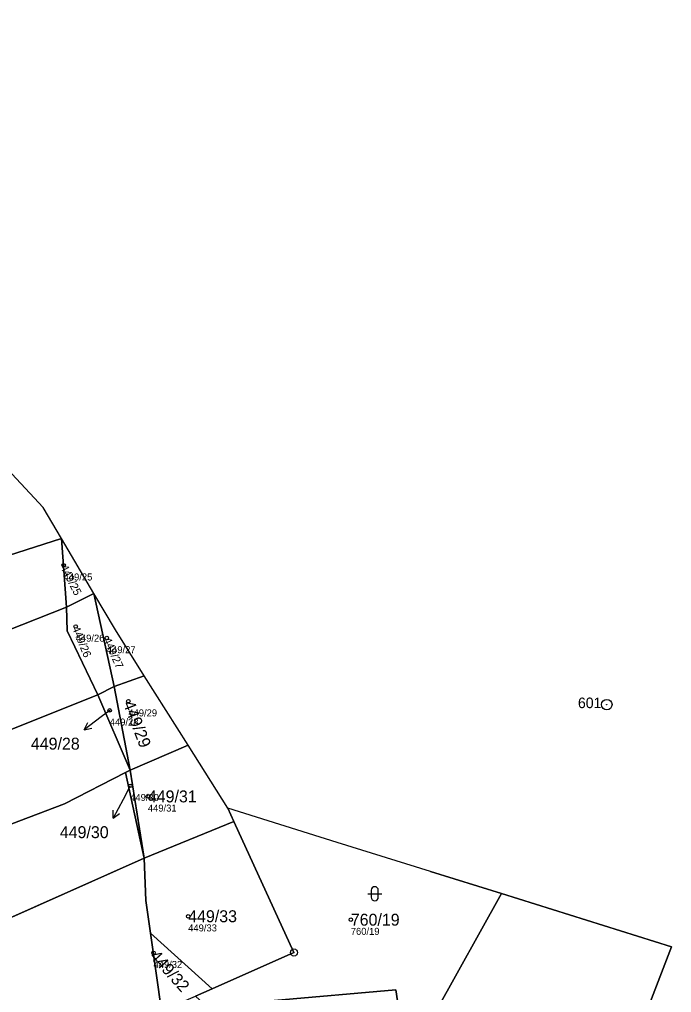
# Model space of a CAD drawing. Extents: x -732749 to -730903, y -1025757 to -1023435.
# Drawn here: x -732119.9 to -732027, y -1025438.1 to -1025299.6 of the extents above; entities that cross this region are included whole.
import ezdxf

# ---------------------------------------------------------------- set-up
doc = ezdxf.new("R2010")
doc.units = 0
for name, color, linetype in [('Definiční body', 7, 'Continuous'), ('Hranice parcel', 7, 'Continuous'), ('Parcelní čísla', 7, 'Continuous'), ('Polygon ku', 7, 'Continuous'), ('Polygon parcely', 7, 'Continuous'), ('Pop  PČ popisy', 7, 'Continuous'), ('Značky bodu BP', 7, 'Continuous'), ('Značky kultur', 7, 'Continuous')]:
    doc.layers.add(name, color=color, linetype=linetype)

msp = doc.modelspace()

# ---------------------------------------------------------------- linework, layer by layer
at = {"layer": 'Definiční body'}
for centre in [(-732113.58, -1025377.31), (-732111.86, -1025386.02), (-732107.42, -1025387.66), (-732104.36, -1025396.66), (-732107.01, -1025397.96), (-732104.1, -1025408.7), (-732101.58, -1025410.21), (-732095.84, -1025427.27), (-732072.68, -1025427.76), (-732100.78, -1025432.47)]:
    msp.add_circle(centre, 0.25, dxfattribs=at)
at = {"layer": 'Hranice parcel'}
for p, q in [((-732113.17, -1025383.29), (-732113.9, -1025373.49)), ((-732109.28, -1025381.3), (-732113.9, -1025373.49)), ((-732113.17, -1025383.29), (-732109.28, -1025381.3)), ((-732106.38, -1025394.56), (-732109.28, -1025381.3)), ((-732106.38, -1025394.56), (-732102.09, -1025393.02)), ((-732095.85, -1025402.93), (-732102.09, -1025393.02)), ((-732108.7, -1025395.73), (-732106.38, -1025394.56)), ((-732104.11, -1025406.47), (-732106.38, -1025394.56)), ((-732104.11, -1025406.47), (-732108.7, -1025395.73)), ((-732104.11, -1025406.47), (-732095.85, -1025402.93)), ((-732090.2, -1025411.9), (-732095.85, -1025402.93)), ((-732104.75, -1025406.8), (-732104.11, -1025406.47)), ((-732102.11, -1025418.99), (-732104.75, -1025406.8)), ((-732102.11, -1025418.99), (-732104.11, -1025406.47)), ((-732074.64, -1025416.75), (-732090.2, -1025411.9)), ((-732090.2, -1025411.9), (-732089.34, -1025413.78)), ((-732102.11, -1025418.99), (-732089.34, -1025413.78)), ((-732061.31, -1025420.9), (-732074.64, -1025416.75)), ((-732102.11, -1025418.99), (-732162.22, -1025445.77)), ((-732061.31, -1025420.9), (-732051.24, -1025424.04)), ((-732051.24, -1025424.04), (-732027, -1025431.6)), ((-732099.65, -1025440.75), (-732101.2, -1025429.67)), ((-732092.43, -1025437.59), (-732101.2, -1025429.67)), ((-732092.43, -1025437.59), (-732094.81, -1025438.64))]:
    msp.add_line(p, q, dxfattribs=at)
for points in [[(-732113.9, -1025373.49), (-732116.5, -1025369.1), (-732121.55, -1025363.6)], [(-732177.55, -1025394.26), (-732151.69, -1025385.6), (-732113.9, -1025373.49)], [(-732102.09, -1025393.02), (-732106.2, -1025386.5), (-732109.28, -1025381.3)], [(-732173.95, -1025406.19), (-732138.44, -1025393.21), (-732113.17, -1025383.29)], [(-732108.7, -1025395.73), (-732113.08, -1025386.62), (-732113.17, -1025383.29)], [(-732170.66, -1025419.68), (-732145.73, -1025410.51), (-732108.7, -1025395.73)], [(-732167.51, -1025433), (-732135.03, -1025419.42), (-732113.47, -1025411.25), (-732104.75, -1025406.8)], [(-732089.34, -1025413.78), (-732080.77, -1025432.43), (-732092.43, -1025437.59)], [(-732101.2, -1025429.67), (-732101.85, -1025425.02), (-732102.11, -1025418.99)], [(-732051.24, -1025424.04), (-732060.59, -1025440.81), (-732064.61, -1025448.7), (-732066.26, -1025437.73), (-732083.61, -1025439.28), (-732089.22, -1025473.8), (-732109.85, -1025510.98)], [(-732027, -1025431.6), (-732043.93, -1025475.5), (-732069.5, -1025549.4), (-732075.39, -1025561.76)]]:
    msp.add_lwpolyline(points, dxfattribs=at)
at = {"layer": 'Polygon ku'}
msp.add_lwpolyline([(-732043.93, -1025475.5), (-732027, -1025431.6), (-732051.24, -1025424.04), (-732061.31, -1025420.9), (-732074.64, -1025416.75), (-732090.2, -1025411.9), (-732095.85, -1025402.93), (-732102.09, -1025393.02), (-732106.2, -1025386.5), (-732109.28, -1025381.3), (-732113.9, -1025373.49), (-732116.5, -1025369.1), (-732121.55, -1025363.6), (-732130.12, -1025354.26), (-732138.15, -1025345.5), (-732140.2, -1025342.7), (-732149.1, -1025332.5), (-732158.9, -1025322.1), (-732160.1, -1025319.6), (-732168.4, -1025305.8), (-732172.1, -1025299.6)], dxfattribs=at)
at = {"layer": 'Polygon parcely'}
for points in [[(-732116.5, -1025369.1), (-732121.55, -1025363.6), (-732152.34, -1025373.59), (-732181.62, -1025382.77), (-732177.55, -1025394.26), (-732151.69, -1025385.6), (-732113.9, -1025373.49)], [(-732113.17, -1025383.29), (-732113.9, -1025373.49), (-732151.69, -1025385.6), (-732177.55, -1025394.26), (-732173.95, -1025406.19), (-732138.44, -1025393.21)], [(-732113.9, -1025373.49), (-732113.17, -1025383.29), (-732109.28, -1025381.3)], [(-732106.38, -1025394.56), (-732109.28, -1025381.3), (-732113.17, -1025383.29), (-732113.08, -1025386.62), (-732108.7, -1025395.73)], [(-732106.2, -1025386.5), (-732109.28, -1025381.3), (-732106.38, -1025394.56), (-732102.09, -1025393.02)], [(-732113.08, -1025386.62), (-732113.17, -1025383.29), (-732138.44, -1025393.21), (-732173.95, -1025406.19), (-732170.66, -1025419.68), (-732145.73, -1025410.51), (-732108.7, -1025395.73)], [(-732102.09, -1025393.02), (-732106.38, -1025394.56), (-732104.11, -1025406.47), (-732095.85, -1025402.93)], [(-732106.38, -1025394.56), (-732108.7, -1025395.73), (-732104.11, -1025406.47)], [(-732167.51, -1025433), (-732135.03, -1025419.42), (-732113.47, -1025411.25), (-732104.75, -1025406.8), (-732104.11, -1025406.47), (-732108.7, -1025395.73), (-732145.73, -1025410.51), (-732170.66, -1025419.68)], [(-732090.2, -1025411.9), (-732095.85, -1025402.93), (-732104.11, -1025406.47), (-732102.11, -1025418.99), (-732089.34, -1025413.78)], [(-732104.75, -1025406.8), (-732113.47, -1025411.25), (-732135.03, -1025419.42), (-732167.51, -1025433), (-732162.22, -1025445.77), (-732102.11, -1025418.99)], [(-732104.11, -1025406.47), (-732104.75, -1025406.8), (-732102.11, -1025418.99)], [(-732074.64, -1025416.75), (-732090.2, -1025411.9), (-732089.34, -1025413.78), (-732080.77, -1025432.43), (-732092.43, -1025437.59), (-732094.81, -1025438.64), (-732090.77, -1025442.35), (-732087.06, -1025451.42), (-732091.36, -1025468.52), (-732090.85, -1025472.94), (-732109.14, -1025507.75), (-732109.85, -1025510.98), (-732089.22, -1025473.8), (-732083.61, -1025439.28), (-732066.26, -1025437.73), (-732064.61, -1025448.7), (-732060.59, -1025440.81), (-732051.24, -1025424.04), (-732061.31, -1025420.9)], [(-732092.43, -1025437.59), (-732080.77, -1025432.43), (-732089.34, -1025413.78), (-732102.11, -1025418.99), (-732101.85, -1025425.02), (-732101.2, -1025429.67)], [(-732099.65, -1025440.75), (-732101.2, -1025429.67), (-732101.85, -1025425.02), (-732102.11, -1025418.99), (-732162.22, -1025445.77), (-732149.05, -1025462.29)], [(-732076.48, -1025564.05), (-732075.39, -1025561.76), (-732069.5, -1025549.4), (-732043.93, -1025475.5), (-732027, -1025431.6), (-732051.24, -1025424.04), (-732060.59, -1025440.81), (-732064.61, -1025448.7), (-732066.26, -1025437.73), (-732083.61, -1025439.28), (-732089.22, -1025473.8), (-732109.85, -1025510.98), (-732113.22, -1025519.89), (-732117.18, -1025522.81), (-732113.57, -1025541.1), (-732114.55, -1025554.41), (-732121.37, -1025579.76), (-732124.92, -1025592.91), (-732122.79, -1025603.6), (-732121, -1025606.72), (-732116.97, -1025607.4), (-732094.46, -1025584.06), (-732079.25, -1025563.77)], [(-732092.43, -1025437.59), (-732101.2, -1025429.67), (-732099.65, -1025440.75), (-732094.81, -1025438.64)]]:
    msp.add_lwpolyline(points, close=True, dxfattribs=at)
at = {"layer": 'Pop  PČ popisy'}
for p, q in [((-732108.24, -1025398.9), (-732110.64, -1025400.71)), ((-732107.01, -1025397.96), (-732108.24, -1025398.9)), ((-732110.64, -1025400.71), (-732110.14, -1025399.7)), ((-732110.64, -1025400.71), (-732109.54, -1025400.5)), ((-732104.1, -1025408.7), (-732105.12, -1025410.66)), ((-732105.12, -1025410.66), (-732106.53, -1025413.31)), ((-732106.53, -1025413.31), (-732106.5, -1025412.19)), ((-732106.53, -1025413.31), (-732105.62, -1025412.66))]:
    msp.add_line(p, q, dxfattribs=at)
at = {"layer": 'Značky bodu BP'}
for centre, radius in [((-732036.23, -1025397.14), 0.75), ((-732036.23, -1025397.14), 0.03), ((-732080.77, -1025432.43), 0.5), ((-732080.77, -1025432.43), 0.0303)]:
    msp.add_circle(centre, radius, dxfattribs=at)
at = {"layer": 'Značky kultur'}
for p, q in [((-732070.26, -1025424.06), (-732068.26, -1025424.06)), ((-732069.76, -1025423.56), (-732069.76, -1025424.56)), ((-732068.76, -1025424.56), (-732068.76, -1025423.56))]:
    msp.add_line(p, q, dxfattribs=at)
for centre, start, end in [((-732069.26, -1025423.56), 0, 180), ((-732069.26, -1025424.56), 180, 359.9879)]:
    msp.add_arc(centre, 0.5, start, end, dxfattribs=at)

# ---------------------------------------------------------------- texts
at = {"layer": 'Definiční body'}
for s, p in [('449/25', (-732113.58, -1025379.47)), ('449/26', (-732111.86, -1025388.18)), ('449/27', (-732107.42, -1025389.82)), ('449/29', (-732104.36, -1025398.82)), ('449/28', (-732107.01, -1025400.12)), ('449/30', (-732104.1, -1025410.86)), ('449/31', (-732101.58, -1025412.37)), ('449/33', (-732095.84, -1025429.43)), ('760/19', (-732072.68, -1025429.92)), ('449/32', (-732100.78, -1025434.63))]:
    msp.add_text(s, height=1, dxfattribs=at).set_placement(p)
at = {"layer": 'Parcelní čísla'}
for s, height, rotation, p in [('449/25', 1.14, 297, (-732114.09, -1025377.57)), ('449/26', 1.14, 292, (-732112.39, -1025386.23)), ('449/27', 1.14, 294, (-732107.94, -1025387.89)), ('449/29', 1.7, 291, (-732105.15, -1025396.96)), ('449/32', 1.7, 312, (-732101.41, -1025433.04))]:
    msp.add_text(s, height=height, rotation=rotation, dxfattribs=at).set_placement(p)
for s, p in [('449/28', (-732118.24, -1025403.55)), ('449/31', (-732101.58, -1025411.06)), ('449/30', (-732114.12, -1025416.15)), ('449/33', (-732095.84, -1025428.12)), ('760/19', (-732072.68, -1025428.61))]:
    msp.add_text(s, height=1.7, dxfattribs=at).set_placement(p)
at = {"layer": 'Značky bodu BP'}
msp.add_text('601', height=1.5, dxfattribs=at).set_placement((-732040.33, -1025397.64))

doc.saveas('drawing.dxf')
